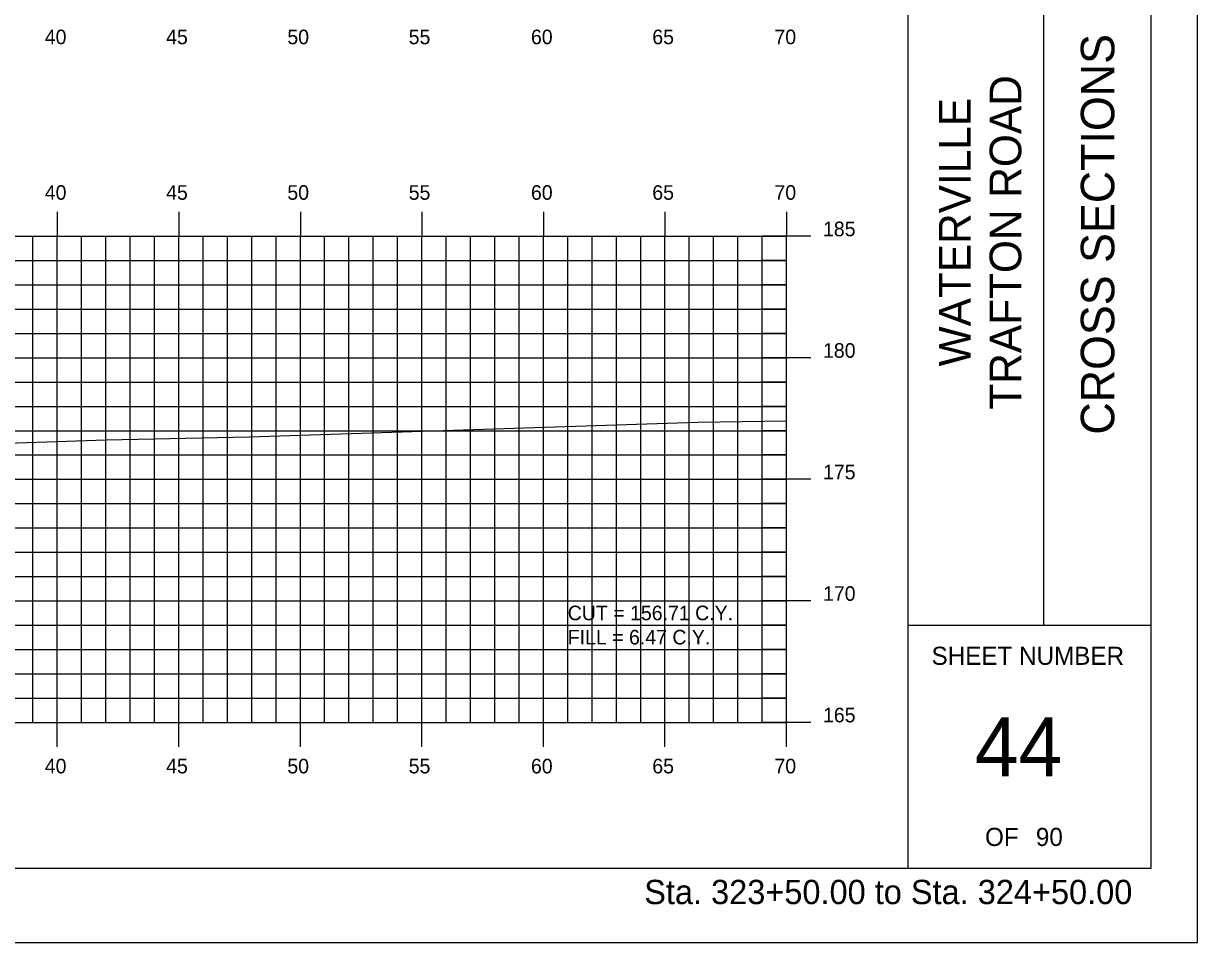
# Model space of a CAD drawing. Extents: x 1140315 to 1140485, y 608981 to 609091.
# Drawn here: x 1140437.1 to 1140485.39, y 608981.28 to 609019.09 of the extents above; entities that cross this region are included whole.
import ezdxf

# ---------------------------------------------------------------- set-up
doc = ezdxf.new("R2010")
doc.units = 0
for name, color, linetype in [('BORDER', 7, 'Continuous'), ('D_Text_Standard', 7, 'Continuous'), ('H_V ANNOTATION', 7, 'Continuous'), ('HIGHWAY_TITLE', 7, 'Continuous'), ('MAJOR', 7, 'Continuous'), ('MINOR', 7, 'Continuous'), ('PLOT BOUNDARY', 7, 'Continuous'), ('S_Roadway_Centerline', 7, 'Continuous')]:
    doc.layers.add(name, color=color, linetype=linetype)

msp = doc.modelspace()

# ---------------------------------------------------------------- linework, layer by layer
at = {"layer": 'BORDER'}
for p, q in [((1140473.488, 608984.335), (1140473.488, 609089.335)), ((1140479.079, 608994.338), (1140479.079, 609029.338)), ((1140473.488, 608994.338), (1140483.488, 608994.338))]:
    msp.add_line(p, q, dxfattribs=at)
msp.add_lwpolyline([(1140323.488, 608984.335), (1140483.488, 608984.335), (1140483.488, 609089.335), (1140323.488, 609089.335)], close=True, dxfattribs=at)
at = {"layer": 'MAJOR'}
for p, q in [((1140438.488, 609011.337), (1140438.488, 609010.335)), ((1140443.488, 609011.337), (1140443.488, 609010.335)), ((1140448.488, 609011.337), (1140448.488, 609010.335)), ((1140453.488, 609011.337), (1140453.488, 609010.335)), ((1140458.488, 609011.337), (1140458.488, 609010.335)), ((1140463.488, 609011.337), (1140463.488, 609010.335)), ((1140468.488, 609011.337), (1140468.488, 609010.335)), ((1140328.488, 609010.335), (1140468.488, 609010.335)), ((1140328.488, 609010.335), (1140468.488, 609010.335)), ((1140438.488, 608990.335), (1140438.488, 609010.335)), ((1140443.488, 608990.335), (1140443.488, 609010.335)), ((1140448.488, 608990.335), (1140448.488, 609010.335)), ((1140453.488, 608990.335), (1140453.488, 609010.335)), ((1140458.488, 608990.335), (1140458.488, 609010.335)), ((1140463.488, 608990.335), (1140463.488, 609010.335)), ((1140469.49, 609010.335), (1140467.486, 609010.335)), ((1140468.488, 608990.335), (1140468.488, 609010.335)), ((1140468.488, 608990.335), (1140468.488, 609010.335)), ((1140328.488, 609005.335), (1140468.488, 609005.335)), ((1140469.49, 609005.335), (1140467.486, 609005.335)), ((1140328.488, 609000.335), (1140468.488, 609000.335)), ((1140469.49, 609000.335), (1140467.486, 609000.335)), ((1140328.488, 608995.335), (1140468.488, 608995.335)), ((1140469.49, 608995.335), (1140467.486, 608995.335)), ((1140328.488, 608990.335), (1140468.488, 608990.335)), ((1140328.488, 608990.335), (1140468.488, 608990.335)), ((1140438.488, 608989.333), (1140438.488, 608990.335)), ((1140443.488, 608989.333), (1140443.488, 608990.335)), ((1140448.488, 608989.333), (1140448.488, 608990.335)), ((1140453.488, 608989.333), (1140453.488, 608990.335)), ((1140458.488, 608989.333), (1140458.488, 608990.335)), ((1140463.488, 608989.333), (1140463.488, 608990.335)), ((1140469.49, 608990.335), (1140467.486, 608990.335)), ((1140468.488, 608989.333), (1140468.488, 608990.335))]:
    msp.add_line(p, q, dxfattribs=at)
at = {"layer": 'MINOR'}
for p, q in [((1140437.488, 608990.335), (1140437.488, 609010.335)), ((1140439.488, 608990.335), (1140439.488, 609010.335)), ((1140440.488, 608990.335), (1140440.488, 609010.335)), ((1140441.488, 608990.335), (1140441.488, 609010.335)), ((1140442.488, 608990.335), (1140442.488, 609010.335)), ((1140444.488, 608990.335), (1140444.488, 609010.335)), ((1140445.488, 608990.335), (1140445.488, 609010.335)), ((1140446.488, 608990.335), (1140446.488, 609010.335)), ((1140447.488, 608990.335), (1140447.488, 609010.335)), ((1140449.488, 608990.335), (1140449.488, 609010.335)), ((1140450.488, 608990.335), (1140450.488, 609010.335)), ((1140451.488, 608990.335), (1140451.488, 609010.335)), ((1140452.488, 608990.335), (1140452.488, 609010.335)), ((1140454.488, 608990.335), (1140454.488, 609010.335)), ((1140455.488, 608990.335), (1140455.488, 609010.335)), ((1140456.488, 608990.335), (1140456.488, 609010.335)), ((1140457.488, 608990.335), (1140457.488, 609010.335)), ((1140459.488, 608990.335), (1140459.488, 609010.335)), ((1140460.488, 608990.335), (1140460.488, 609010.335)), ((1140461.488, 608990.335), (1140461.488, 609010.335)), ((1140462.488, 608990.335), (1140462.488, 609010.335)), ((1140464.488, 608990.335), (1140464.488, 609010.335)), ((1140465.488, 608990.335), (1140465.488, 609010.335)), ((1140466.488, 608990.335), (1140466.488, 609010.335)), ((1140467.488, 608990.335), (1140467.488, 609010.335)), ((1140328.488, 609009.335), (1140468.488, 609009.335)), ((1140468.488, 609009.335), (1140467.486, 609009.335)), ((1140328.488, 609008.335), (1140468.488, 609008.335)), ((1140468.488, 609008.335), (1140467.486, 609008.335)), ((1140328.488, 609007.335), (1140468.488, 609007.335)), ((1140468.488, 609007.335), (1140467.486, 609007.335)), ((1140328.488, 609006.335), (1140468.488, 609006.335)), ((1140468.488, 609006.335), (1140467.486, 609006.335)), ((1140328.488, 609004.335), (1140468.488, 609004.335)), ((1140468.488, 609004.335), (1140467.486, 609004.335)), ((1140328.488, 609003.335), (1140468.488, 609003.335)), ((1140468.488, 609003.335), (1140467.486, 609003.335)), ((1140328.488, 609002.335), (1140468.488, 609002.335)), ((1140468.488, 609002.335), (1140467.486, 609002.335)), ((1140328.488, 609001.335), (1140468.488, 609001.335)), ((1140468.488, 609001.335), (1140467.486, 609001.335)), ((1140328.488, 608999.335), (1140468.488, 608999.335)), ((1140468.488, 608999.335), (1140467.486, 608999.335)), ((1140328.488, 608998.335), (1140468.488, 608998.335)), ((1140468.488, 608998.335), (1140467.486, 608998.335)), ((1140328.488, 608997.335), (1140468.488, 608997.335)), ((1140468.488, 608997.335), (1140467.486, 608997.335)), ((1140328.488, 608996.335), (1140468.488, 608996.335)), ((1140468.488, 608996.335), (1140467.486, 608996.335)), ((1140328.488, 608994.335), (1140468.488, 608994.335)), ((1140468.488, 608994.335), (1140467.486, 608994.335)), ((1140328.488, 608993.335), (1140468.488, 608993.335)), ((1140468.488, 608993.335), (1140467.486, 608993.335)), ((1140328.488, 608992.335), (1140468.488, 608992.335)), ((1140468.488, 608992.335), (1140467.486, 608992.335)), ((1140328.488, 608991.335), (1140468.488, 608991.335)), ((1140468.488, 608991.335), (1140467.486, 608991.335))]:
    msp.add_line(p, q, dxfattribs=at)
at = {"layer": 'PLOT BOUNDARY'}
msp.add_lwpolyline([(1140315.395, 608981.276), (1140485.395, 608981.276), (1140485.395, 609091.276), (1140315.395, 609091.276)], close=True, dxfattribs=at)
at = {"layer": 'S_Roadway_Centerline'}
msp.add_lwpolyline([(1140367.542, 608998.327), (1140370.795, 608998.559), (1140377.85, 608999.184), (1140382.728, 609001.243), (1140384.55, 609001.921), (1140386.861, 609002.265), (1140387.461, 609002.383), (1140389.636, 609002.458), (1140393.842, 609002.696), (1140398.506, 609003.008), (1140403.767, 609002.674), (1140409.646, 609002.543), (1140411.009, 609002.36), (1140411.793, 609002.182), (1140414.446, 609001.638), (1140417.551, 609001.002), (1140420.367, 609001.06), (1140422.978, 609001.362), (1140440.501, 609001.955), (1140446.381, 609002.087), (1140464.846, 609002.691), (1140468.488, 609002.74)], dxfattribs=at)

# ---------------------------------------------------------------- texts
at = {"layer": 'BORDER'}
msp.add_text('CROSS SECTIONS', height=1.37787, rotation=90, dxfattribs=at).set_placement((1140481.973, 609002.172))
for s, height, p in [('SHEET NUMBER', 0.74527, (1140474.454, 608992.701)), ('44', 2.4194, (1140476.235, 608988.118)), ('OF', 0.7453, (1140476.655, 608985.248)), ('90', 0.7453, (1140478.745, 608985.248))]:
    msp.add_text(s, height=height, dxfattribs=at).set_placement(p)
at = {"layer": 'D_Text_Standard'}
for s, p in [('CUT = 156.71 C.Y.', (1140459.488, 608994.535)), ('FILL = 6.47 C.Y.', (1140459.488, 608993.539))]:
    msp.add_text(s, height=0.6, dxfattribs=at).set_placement(p)
at = {"layer": 'H_V ANNOTATION'}
for s, height, p in [('40', 0.6, (1140437.974, 609018.235)), ('45', 0.6, (1140442.966, 609018.235)), ('50', 0.6, (1140447.953, 609018.235)), ('55', 0.6, (1140452.945, 609018.235)), ('60', 0.6, (1140457.974, 609018.235)), ('65', 0.6, (1140462.966, 609018.235)), ('70', 0.6, (1140467.99, 609018.235)), ('40', 0.6, (1140437.974, 609011.835)), ('45', 0.6, (1140442.966, 609011.835)), ('50', 0.6, (1140447.953, 609011.835)), ('55', 0.6, (1140452.945, 609011.835)), ('60', 0.6, (1140457.974, 609011.835)), ('65', 0.6, (1140462.966, 609011.835)), ('70', 0.6, (1140467.99, 609011.835)), ('185', 0.6, (1140469.988, 609010.335)), ('180', 0.6, (1140469.988, 609005.335)), ('175', 0.6, (1140469.988, 609000.335)), ('170', 0.6, (1140469.988, 608995.335)), ('165', 0.6, (1140469.988, 608990.335)), ('40', 0.6, (1140437.974, 608988.235)), ('45', 0.6, (1140442.966, 608988.235)), ('50', 0.6, (1140447.953, 608988.235)), ('55', 0.6, (1140452.945, 608988.235)), ('60', 0.6, (1140457.974, 608988.235)), ('65', 0.6, (1140462.966, 608988.235)), ('70', 0.6, (1140467.99, 608988.235)), ('Sta. 323+50.00 to Sta. 324+50.00', 1.0002, (1140462.634, 608982.855))]:
    msp.add_text(s, height=height, dxfattribs=at).set_placement(p)
at = {"layer": 'HIGHWAY_TITLE'}
for s, height, p in [('TRAFTON ROAD', 1.30428, (1140478.147, 609003.201)), ('WATERVILLE', 1.3043, (1140476.061, 609004.98))]:
    msp.add_text(s, height=height, rotation=90, dxfattribs=at).set_placement(p)

doc.saveas('drawing.dxf')
